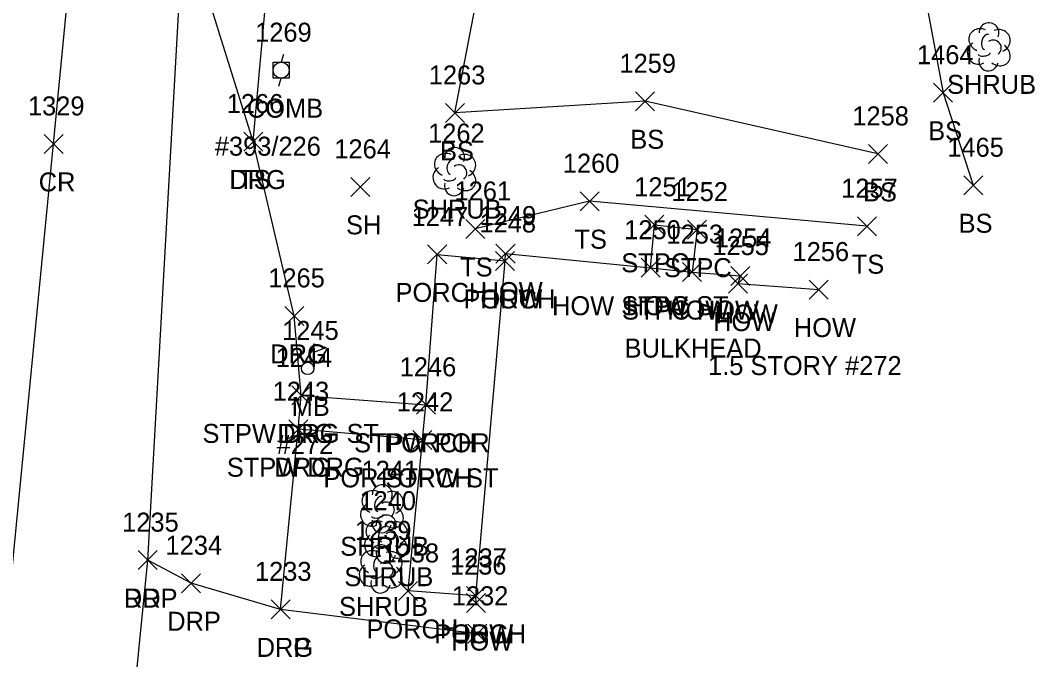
# Model space of a CAD drawing. Extents: x 1653908 to 1654393, y 539913 to 544256.
# Drawn here: x 1654041 to 1654147.8, y 541355.4 to 541422.7 of the extents above; entities that cross this region are included whole.
import ezdxf

# ---------------------------------------------------------------- set-up
doc = ezdxf.new("R2010")
doc.units = 0
for name, color, linetype in [('L_A', 7, 'Continuous'), ('L_C', 7, 'Continuous'), ('L_I', 7, 'Continuous'), ('L_TIC', 7, 'Continuous'), ('LBC', 7, 'Continuous'), ('LBF', 7, 'Continuous'), ('LELB', 7, 'Continuous'), ('LMB', 7, 'Continuous'), ('LSH', 7, 'Continuous'), ('P_A', 7, 'Continuous'), ('P_I', 7, 'Continuous'), ('P_TIC', 7, 'Continuous'), ('PET', 7, 'Continuous'), ('PRC', 7, 'Continuous'), ('R_A', 7, 'Continuous'), ('R_I', 7, 'Continuous'), ('R_TIC', 7, 'Continuous'), ('RDG', 7, 'Continuous'), ('RDP', 7, 'Continuous'), ('U_A', 7, 'Continuous'), ('U_C', 7, 'Continuous'), ('U_I', 7, 'Continuous'), ('UP', 7, 'Continuous')]:
    doc.layers.add(name, color=color, linetype=linetype)

msp = doc.modelspace()

# ---------------------------------------------------------------- linework, layer by layer
at = {"layer": 'L_TIC'}
for points in [[(1654105.78, 541413.13), (1654107.78, 541415.13)], [(1654107.78, 541413.13), (1654105.78, 541415.13)], [(1654137.12, 541414.03), (1654139.12, 541416.03)], [(1654139.12, 541414.03), (1654137.12, 541416.03)], [(1654085.76, 541411.9), (1654087.76, 541413.9)], [(1654087.76, 541411.9), (1654085.76, 541413.9)], [(1654064.55, 541408.89), (1654066.55, 541410.89)], [(1654066.55, 541408.89), (1654064.55, 541410.89)], [(1654130.27, 541407.59), (1654132.27, 541409.59)], [(1654132.27, 541407.59), (1654130.27, 541409.59)], [(1654075.82, 541404.12), (1654077.82, 541406.12)], [(1654077.82, 541404.12), (1654075.82, 541406.12)], [(1654140.31, 541404.29), (1654142.31, 541406.29)], [(1654142.31, 541404.29), (1654140.31, 541406.29)], [(1654099.94, 541402.61), (1654101.94, 541404.61)], [(1654101.94, 541402.61), (1654099.94, 541404.61)], [(1654087.91, 541399.69), (1654089.91, 541401.69)], [(1654089.91, 541399.69), (1654087.91, 541401.69)], [(1654106.75, 541400.13), (1654108.75, 541402.13)], [(1654108.75, 541400.13), (1654106.75, 541402.13)], [(1654111.24, 541399.62), (1654113.24, 541401.62)], [(1654113.24, 541399.62), (1654111.24, 541401.62)], [(1654129.11, 541399.98), (1654131.11, 541401.98)], [(1654131.11, 541399.98), (1654129.11, 541401.98)], [(1654091.09, 541397.1), (1654093.09, 541399.1)], [(1654093.09, 541397.1), (1654091.09, 541399.1)], [(1654083.9, 541397.01), (1654085.9, 541399.01)], [(1654085.9, 541397.01), (1654083.9, 541399.01)], [(1654091.05, 541396.32), (1654093.05, 541398.32)], [(1654093.05, 541396.32), (1654091.05, 541398.32)], [(1654091.05, 541396.32), (1654093.05, 541398.32)], [(1654093.05, 541396.32), (1654091.05, 541398.32)], [(1654106.36, 541395.61), (1654108.36, 541397.61)], [(1654108.36, 541395.61), (1654106.36, 541397.61)], [(1654106.36, 541395.61), (1654108.36, 541397.61)], [(1654108.36, 541395.61), (1654106.36, 541397.61)], [(1654110.72, 541395.15), (1654112.72, 541397.15)], [(1654112.72, 541395.15), (1654110.72, 541397.15)], [(1654110.72, 541395.15), (1654112.72, 541397.15)], [(1654112.72, 541395.15), (1654110.72, 541397.15)], [(1654115.54, 541393.94), (1654117.54, 541395.94)], [(1654117.54, 541393.94), (1654115.54, 541395.94)], [(1654115.81, 541394.74), (1654117.81, 541396.74)], [(1654117.81, 541394.74), (1654115.81, 541396.74)], [(1654124.04, 541393.31), (1654126.04, 541395.31)], [(1654126.04, 541393.31), (1654124.04, 541395.31)], [(1654069.6, 541382.17), (1654071.6, 541384.17)], [(1654071.6, 541382.17), (1654069.6, 541384.17)], [(1654082.71, 541381.18), (1654084.71, 541383.18)], [(1654084.71, 541381.18), (1654082.71, 541383.18)], [(1654082.71, 541381.18), (1654084.71, 541383.18)], [(1654084.71, 541381.18), (1654082.71, 541383.18)], [(1654069.29, 541378.61), (1654071.29, 541380.61)], [(1654071.29, 541378.61), (1654069.29, 541380.61)], [(1654082.34, 541377.49), (1654084.34, 541379.49)], [(1654084.34, 541377.49), (1654082.34, 541379.49)], [(1654082.34, 541377.49), (1654084.34, 541379.49)], [(1654084.34, 541377.49), (1654082.34, 541379.49)], [(1654080.84, 541361.59), (1654082.84, 541363.59)], [(1654082.84, 541361.59), (1654080.84, 541363.59)], [(1654087.98, 541361.07), (1654089.98, 541363.07)], [(1654089.98, 541361.07), (1654087.98, 541363.07)], [(1654087.98, 541361.07), (1654089.98, 541363.07)], [(1654089.98, 541361.07), (1654087.98, 541363.07)], [(1654087.99, 541360.31), (1654089.99, 541362.31)], [(1654089.99, 541360.31), (1654087.99, 541362.31)]]:
    msp.add_lwpolyline(points, dxfattribs=at)
at = {"layer": 'LBC'}
msp.add_lwpolyline([(1654088.99, 541361.31), (1654088.98, 541362.07), (1654092.05, 541397.32), (1654092.09, 541398.1), (1654107.36, 541396.61), (1654111.72, 541396.15), (1654116.81, 541395.74), (1654116.54, 541394.94), (1654125.04, 541394.31)], dxfattribs=at)
at = {"layer": 'LBF'}
for points in [[(1654107.36, 541396.61), (1654107.75, 541401.13), (1654112.24, 541400.62), (1654111.72, 541396.15)], [(1654088.98, 541362.07), (1654081.84, 541362.59), (1654083.34, 541378.49), (1654083.71, 541382.18), (1654084.9, 541398.01), (1654092.05, 541397.32)], [(1654083.34, 541378.49), (1654070.29, 541379.61), (1654070.6, 541383.17), (1654083.71, 541382.18)]]:
    msp.add_lwpolyline(points, dxfattribs=at)
at = {"layer": 'LELB'}
for points in [[(1654065.55, 541409.89), (1654067.54, 541432.12), (1654070.2, 541467.91), (1654070.34, 541474.94), (1654070.4, 541508.69), (1654072.4, 541525.84), (1654075.32, 541545.16), (1654075.45, 541573)], [(1654131.27, 541408.59), (1654106.78, 541414.13), (1654086.76, 541412.9), (1654094.61, 541453.8), (1654098.52, 541491.53)], [(1654133.22, 541441.21), (1654138.12, 541415.03), (1654141.31, 541405.29)], [(1654130.11, 541400.98), (1654100.94, 541403.61), (1654088.91, 541400.69)]]:
    msp.add_lwpolyline(points, dxfattribs=at)
at = {"layer": 'LMB'}
for p, q in [((1654071.93, 541388.61), (1654073.23, 541388.22)), ((1654071.94, 541386.01), (1654071.94, 541388.61)), ((1654071.94, 541387.71), (1654073.22, 541388.22)), ((1654071.28, 541386.01), (1654071.28, 541386.01))]:
    msp.add_line(p, q, dxfattribs=at)
msp.add_circle((1654071.28, 541386.01), 0.656, dxfattribs=at)
at = {"layer": 'LSH'}
for p, q in [((1654142.92, 541419.91), (1654142.92, 541419.91)), ((1654142.92, 541419.91), (1654142.92, 541419.91)), ((1654086.69, 541406.78), (1654086.69, 541406.78)), ((1654086.69, 541406.78), (1654086.69, 541406.78)), ((1654079.07, 541371.29), (1654079.07, 541371.29)), ((1654079.07, 541371.29), (1654079.07, 541371.29)), ((1654079.5, 541368.09), (1654079.5, 541368.09)), ((1654079.5, 541368.09), (1654079.5, 541368.09)), ((1654078.95, 541364.96), (1654078.95, 541364.96)), ((1654078.95, 541364.96), (1654078.95, 541364.96))]:
    msp.add_line(p, q, dxfattribs=at)
for centre in [(1654142.96, 541421.34), (1654086.74, 541408.21), (1654079.12, 541372.72), (1654079.54, 541369.53), (1654078.99, 541366.39)]:
    msp.add_arc(centre, 1.05, 335.5272, 180.9563, dxfattribs=at)
for centre, major_axis, ratio, start_param, end_param in [((1654142.13, 541420.57), (1.21, -0.51), 0.895232, 1.570796, 4.712389), ((1654143.96, 541420.49), (-1.14, -0.48), 0.949671, 1.570796, 4.712389), ((1654142.71, 541420.37), (-0.208, -0.792), 0.645439, 3.141593, 6.283185), ((1654143.42, 541419.74), (-0.5, 0.667), 0.989748, 3.141593, 6.283185), ((1654141.83, 541419.2), (0.58, -1.04), 0.959034, 3.141593, 6.283185), ((1654143.92, 541419.08), (-1.09, 0.79), 0.841452, 1.570796, 4.712389), ((1654142.92, 541418.41), (0.26, 1.06), 0.942809, 1.570796, 4.712389), ((1654142.46, 541419.16), (-0.625, -0.083), 0.423636, 0, 3.141593), ((1654085.9, 541407.44), (1.21, -0.51), 0.895232, 1.570796, 4.712389), ((1654087.73, 541407.36), (-1.14, -0.48), 0.949671, 1.570796, 4.712389), ((1654086.48, 541407.23), (-0.208, -0.792), 0.645439, 3.141593, 6.283185), ((1654085.61, 541406.07), (0.58, -1.04), 0.959034, 3.141593, 6.283185), ((1654087.19, 541406.61), (-0.5, 0.667), 0.989748, 3.141593, 6.283185), ((1654087.69, 541405.94), (-1.09, 0.79), 0.841452, 1.570796, 4.712389), ((1654086.69, 541405.28), (0.26, 1.06), 0.942809, 1.570796, 4.712389), ((1654086.23, 541406.03), (-0.625, -0.083), 0.423636, 0, 3.141593), ((1654078.28, 541371.95), (1.21, -0.51), 0.895232, 1.570796, 4.712389), ((1654078.86, 541371.74), (-0.208, -0.792), 0.645439, 3.141593, 6.283185), ((1654080.11, 541371.87), (-1.14, -0.48), 0.949671, 1.570796, 4.712389), ((1654077.99, 541370.58), (0.58, -1.04), 0.959034, 3.141593, 6.283185), ((1654079.57, 541371.12), (-0.5, 0.667), 0.989748, 3.141593, 6.283185), ((1654080.07, 541370.45), (-1.09, 0.79), 0.841452, 1.570796, 4.712389), ((1654078.61, 541370.54), (-0.625, -0.083), 0.423636, 0, 3.141593), ((1654078.7, 541368.76), (1.21, -0.51), 0.895232, 1.570796, 4.712389), ((1654079.07, 541369.79), (0.26, 1.06), 0.942809, 1.570796, 4.712389), ((1654079.29, 541368.55), (-0.208, -0.792), 0.645439, 3.141593, 6.283185), ((1654080.54, 541368.68), (-1.14, -0.48), 0.949671, 1.570796, 4.712389), ((1654078.41, 541367.38), (0.58, -1.04), 0.959034, 3.141593, 6.283185), ((1654080, 541367.93), (-0.5, 0.667), 0.989748, 3.141593, 6.283185), ((1654080.5, 541367.26), (-1.09, 0.79), 0.841452, 1.570796, 4.712389), ((1654079.04, 541367.34), (-0.625, -0.083), 0.423636, 0, 3.141593), ((1654078.15, 541365.63), (1.21, -0.51), 0.895232, 1.570796, 4.712389), ((1654078.74, 541365.42), (-0.208, -0.792), 0.645439, 3.141593, 6.283185), ((1654079.5, 541366.59), (0.26, 1.06), 0.942809, 1.570796, 4.712389), ((1654079.99, 541365.54), (-1.14, -0.48), 0.949671, 1.570796, 4.712389), ((1654077.86, 541364.25), (0.58, -1.04), 0.959034, 3.141593, 6.283185), ((1654079.45, 541364.79), (-0.5, 0.667), 0.989748, 3.141593, 6.283185), ((1654079.95, 541364.13), (-1.09, 0.79), 0.841452, 1.570796, 4.712389), ((1654078.49, 541364.21), (-0.625, -0.083), 0.423636, 0, 3.141593), ((1654078.95, 541363.46), (0.26, 1.06), 0.942809, 1.570796, 4.712389)]:
    msp.add_ellipse(centre, major_axis=major_axis, ratio=ratio, start_param=start_param, end_param=end_param, dxfattribs=at)
at = {"layer": 'P_TIC'}
for points in [[(1654043.55, 541408.64), (1654045.55, 541410.64)], [(1654045.55, 541408.64), (1654043.55, 541410.64)], [(1654053.45, 541364.83), (1654055.45, 541366.83)], [(1654055.45, 541364.83), (1654053.45, 541366.83)]]:
    msp.add_lwpolyline(points, dxfattribs=at)
at = {"layer": 'PET'}
msp.add_lwpolyline([(1654026.62, 541021.77), (1654028.54, 541070.24), (1654031.49, 541127.98), (1654037.66, 541208.54), (1654042.53, 541248.32), (1654044.37, 541265.21), (1654043.73, 541271.44), (1654047, 541298.33), (1654052.52, 541346.47), (1654054.45, 541365.83), (1654058.25, 541433.29), (1654064.32, 541497.28)], dxfattribs=at)
at = {"layer": 'PRC'}
msp.add_lwpolyline([(1654015.22, 541022.42), (1654016.68, 541078.09), (1654019.78, 541129.03), (1654023.08, 541180.04), (1654025.54, 541208.79), (1654028.97, 541248.66), (1654033.81, 541299.54), (1654044.55, 541409.64), (1654048.4, 541449.61), (1654049.07, 541458.74), (1654052.54, 541493.4), (1654055.94, 541523.17), (1654060.18, 541564.47), (1654062.59, 541587.52)], dxfattribs=at)
at = {"layer": 'R_TIC'}
for points in [[(1654064.55, 541408.89), (1654066.55, 541410.89)], [(1654066.55, 541408.89), (1654064.55, 541410.89)], [(1654068.87, 541390.54), (1654070.87, 541392.54)], [(1654070.87, 541390.54), (1654068.87, 541392.54)], [(1654069.6, 541382.17), (1654071.6, 541384.17)], [(1654071.6, 541382.17), (1654069.6, 541384.17)], [(1654069.29, 541378.61), (1654071.29, 541380.61)], [(1654071.29, 541378.61), (1654069.29, 541380.61)], [(1654053.45, 541364.83), (1654055.45, 541366.83)], [(1654055.45, 541364.83), (1654053.45, 541366.83)], [(1654058.01, 541362.4), (1654060.01, 541364.4)], [(1654060.01, 541362.4), (1654058.01, 541364.4)], [(1654067.42, 541359.65), (1654069.42, 541361.65)], [(1654069.42, 541359.65), (1654067.42, 541361.65)], [(1654067.42, 541359.65), (1654069.42, 541361.65)], [(1654069.42, 541359.65), (1654067.42, 541361.65)], [(1654088.13, 541357.08), (1654090.13, 541359.08)], [(1654090.13, 541357.08), (1654088.13, 541359.08)]]:
    msp.add_lwpolyline(points, dxfattribs=at)
at = {"layer": 'RDG'}
for points in [[(1654070.6, 541383.17), (1654069.87, 541391.54), (1654065.55, 541409.89), (1654058.25, 541433.29)], [(1654068.42, 541360.65), (1654070.29, 541379.61)]]:
    msp.add_lwpolyline(points, dxfattribs=at)
at = {"layer": 'RDP'}
msp.add_lwpolyline([(1654089.13, 541358.08), (1654068.42, 541360.65), (1654059.01, 541363.4), (1654054.45, 541365.83)], dxfattribs=at)
at = {"layer": 'UP'}
for p, q in [((1654068.74, 541419.07), (1654068.49, 541418.23)), ((1654067.66, 541416.57), (1654067.66, 541418.23)), ((1654067.66, 541418.23), (1654069.33, 541418.23)), ((1654068.49, 541417.4), (1654068.49, 541417.4)), ((1654069.33, 541418.23), (1654069.33, 541416.57)), ((1654069.33, 541416.57), (1654067.66, 541416.57)), ((1654068.24, 541415.73), (1654068.49, 541416.57))]:
    msp.add_line(p, q, dxfattribs=at)
msp.add_circle((1654068.49, 541417.4), 0.833, dxfattribs=at)

# ---------------------------------------------------------------- texts
at = {"layer": 'L_A'}
for s, p in [('SHRUB', (1654138.55, 541414.91)), ('BS', (1654136.56, 541410.03)), ('BS', (1654105.22, 541409.13)), ('BS', (1654085.2, 541407.9)), ('TS', (1654063.96, 541404.89)), ('BS', (1654129.71, 541403.59)), ('SHRUB', (1654082.32, 541401.78)), ('BS', (1654139.76, 541400.29)), ('SH', (1654075.31, 541400.12)), ('TS', (1654099.35, 541398.61)), ('STPC', (1654104.27, 541396.13)), ('TS', (1654128.52, 541395.98)), ('TS', (1654087.32, 541395.69)), ('STPC', (1654108.76, 541395.62)), ('PORCH', (1654080.52, 541393.01)), ('HOW', (1654089.47, 541393.1)), ('PORCH', (1654087.67, 541392.32)), ('HOW', (1654089.43, 541392.32)), ('HOW STPC ST', (1654096.99, 541391.61)), ('STPC HOW', (1654104.35, 541391.15)), ('HOW', (1654104.75, 541391.61)), ('HOW', (1654109.1, 541391.15)), ('HOW', (1654114.2, 541390.74)), ('HOW', (1654113.93, 541389.94)), ('HOW', (1654122.43, 541389.31)), ('MB', (1654069.59, 541381.01)), ('STPW DRG ST', (1654060.21, 541378.17)), ('STPW POR', (1654076.16, 541377.18)), ('PORCH', (1654079.33, 541377.18)), ('STPW DRG', (1654062.77, 541374.61)), ('POR STPW ST', (1654072.93, 541373.49)), ('PORCH', (1654078.97, 541373.49)), ('SHRUB', (1654074.7, 541366.29)), ('SHRUB', (1654075.13, 541363.09)), ('SHRUB', (1654074.58, 541359.96)), ('PORCH', (1654077.46, 541357.59)), ('PORCH', (1654084.6, 541357.07)), ('HOW', (1654086.37, 541357.07)), ('HOW', (1654086.37, 541356.31))]:
    msp.add_text(s, height=2, dxfattribs=at).set_placement(p)
at = {"layer": 'L_C'}
for s, p in [('BULKHEAD', (1654104.62, 541387.15)), ('1.5 STORY #272', (1654113.4, 541385.31)), ('#272', (1654068.02, 541377.01))]:
    msp.add_text(s, height=2, dxfattribs=at).set_placement(p)
at = {"layer": 'L_I'}
for s, p in [('1464', (1654135.38, 541418.03)), ('1259', (1654104.08, 541417.13)), ('1263', (1654084.02, 541415.9)), ('1266', (1654062.76, 541412.89)), ('1258', (1654128.58, 541411.59)), ('1262', (1654083.95, 541409.78)), ('1264', (1654074.08, 541408.12)), ('1465', (1654138.57, 541408.29)), ('1260', (1654098.12, 541406.61)), ('1261', (1654086.73, 541403.69)), ('1251', (1654105.63, 541404.13)), ('1252', (1654109.55, 541403.62)), ('1257', (1654127.41, 541403.98)), ('1247', (1654082.21, 541401.01)), ('1248', (1654089.35, 541400.32)), ('1248', (1654089.35, 541400.32)), ('1249', (1654089.38, 541401.1)), ('1250', (1654104.58, 541399.61)), ('1250', (1654104.58, 541399.61)), ('1253', (1654109.03, 541399.15)), ('1253', (1654109.03, 541399.15)), ('1254', (1654114.12, 541398.74)), ('1255', (1654113.85, 541397.94)), ('1256', (1654122.29, 541397.31)), ('1245', (1654068.59, 541389.01)), ('1244', (1654067.91, 541386.17)), ('1246', (1654080.96, 541385.18)), ('1246', (1654080.96, 541385.18)), ('1243', (1654067.59, 541382.61)), ('1242', (1654080.65, 541381.49)), ('1242', (1654080.65, 541381.49)), ('1241', (1654076.94, 541374.29)), ('1240', (1654076.72, 541371.09)), ('1239', (1654076.25, 541367.96)), ('1238', (1654079.15, 541365.59)), ('1237', (1654086.29, 541365.07)), ('1237', (1654086.29, 541365.07)), ('1236', (1654086.24, 541364.31))]:
    msp.add_text(s, height=2, dxfattribs=at).set_placement(p)
at = {"layer": 'P_A'}
for s, p in [('CR', (1654042.98, 541404.64)), ('RDP', (1654051.94, 541360.83))]:
    msp.add_text(s, height=2, dxfattribs=at).set_placement(p)
at = {"layer": 'P_I'}
for s, p in [('1329', (1654041.85, 541412.64)), ('1235', (1654051.76, 541368.83))]:
    msp.add_text(s, height=2, dxfattribs=at).set_placement(p)
at = {"layer": 'R_A'}
for s, p in [('DRG', (1654063.04, 541404.89)), ('DRG', (1654067.35, 541386.54)), ('DRG', (1654068.09, 541378.17)), ('DRG', (1654067.77, 541374.61)), ('DRP', (1654051.94, 541360.83)), ('DRP', (1654056.5, 541358.4)), ('DRG', (1654065.91, 541355.65)), ('DRP', (1654065.91, 541355.65))]:
    msp.add_text(s, height=2, dxfattribs=at).set_placement(p)
at = {"layer": 'R_I'}
for s, p in [('1266', (1654062.76, 541412.89)), ('1265', (1654067.13, 541394.54)), ('1244', (1654067.91, 541386.17)), ('1243', (1654067.59, 541382.61)), ('1235', (1654051.76, 541368.83)), ('1234', (1654056.32, 541366.4)), ('1233', (1654065.73, 541363.65)), ('1233', (1654065.73, 541363.65)), ('1232', (1654086.44, 541361.08))]:
    msp.add_text(s, height=2, dxfattribs=at).set_placement(p)
at = {"layer": 'U_A'}
msp.add_text('COMB', height=2, dxfattribs=at).set_placement((1654064.88, 541412.4))
at = {"layer": 'U_C'}
msp.add_text('#393/226', height=2, dxfattribs=at).set_placement((1654061.51, 541408.4))
at = {"layer": 'U_I'}
msp.add_text('1269', height=2, dxfattribs=at).set_placement((1654065.75, 541420.4))

doc.saveas('drawing.dxf')
